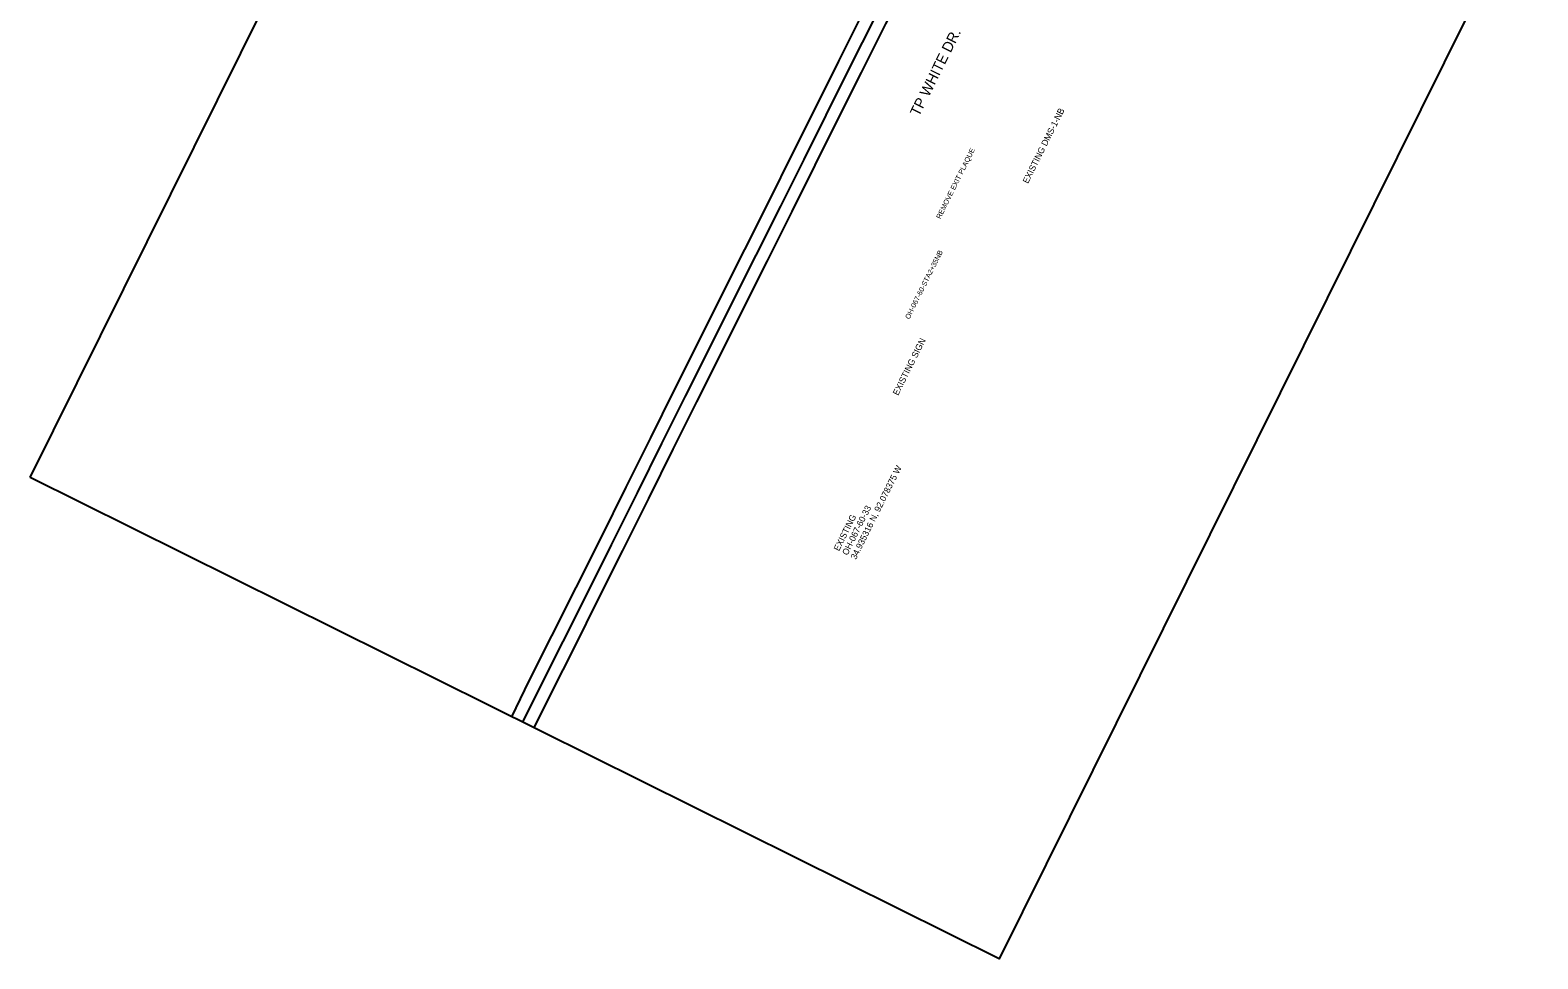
# Model space of a CAD drawing. Extents: x 1288247 to 1295361, y 218673 to 226414.
# Drawn here: x 1288247 to 1289679, y 218673 to 219555 of the extents above; entities that cross this region are included whole.
import ezdxf

# ---------------------------------------------------------------- set-up
doc = ezdxf.new("R2010")
doc.units = 0
for name, color, linetype in [('40', 7, 'Continuous'), ('Plan Notes', 7, 'Continuous'), ('R_Annotation', 7, 'Continuous'), ('R_No Plot', 7, 'Continuous'), ('R_Striping_Existing', 7, 'Continuous'), ('S_EDGE_PAVEMENT', 7, 'Continuous')]:
    doc.layers.add(name, color=color, linetype=linetype)

msp = doc.modelspace()

# ---------------------------------------------------------------- linework, layer by layer
at = {"layer": 'R_No Plot'}
msp.add_lwpolyline([(1288247.2, 219130.2), (1288758.7, 220160.2), (1289678.8, 219703.3), (1289167.3, 218673.3)], close=True, dxfattribs=at)
at = {"layer": 'R_Striping_Existing'}
for points in [[(1288704.4, 218903.1), (1288721.1, 218937.1), (1288742.4, 218979.7), (1288765.5, 219025.6), (1288788.6, 219071.6), (1288813.1, 219120.9), (1288836.4, 219167.7), (1288858.7, 219212.5), (1288881.1, 219257.4), (1288903.1, 219301.3), (1288925.8, 219346.5), (1288949.2, 219393.1), (1288971.2, 219437.3), (1288992.2, 219479.2), (1289015.1, 219525.1), (1289038.3, 219571.5), (1289061.2, 219617.1), (1289082.9, 219660.9), (1289105.4, 219706.1), (1289128.5, 219752.4), (1289151.4, 219798.2), (1289169.8, 219835.2), (1289192.8, 219881), (1289218.3, 219932)], [(1288715.1, 218897.8), (1288731.9, 218931.7), (1288753.2, 218974.3), (1288776.3, 219020.2), (1288799.3, 219066.3), (1288823.9, 219115.6), (1288847.1, 219162.3), (1288869.5, 219207.2), (1288891.9, 219252), (1288913.8, 219295.9), (1288936.6, 219341.1), (1288959.9, 219387.7), (1288982, 219431.9), (1289002.9, 219473.8), (1289025.9, 219519.7), (1289049.1, 219566.1), (1289071.9, 219611.8), (1289093.6, 219655.5), (1289116.2, 219700.7), (1289139.2, 219747), (1289162.1, 219792.9), (1289180.6, 219829.8), (1289203.5, 219875.6), (1289229, 219926.7)]]:
    msp.add_lwpolyline(points, dxfattribs=at)
at = {"layer": 'S_EDGE_PAVEMENT'}
msp.add_lwpolyline([(1288725.9, 218892.5), (1288742.6, 218926.4), (1288763.9, 218968.9), (1288787, 219014.9), (1288810, 219060.9), (1288834.6, 219110.2), (1288857.8, 219157), (1288880.2, 219201.8), (1288902.6, 219246.6), (1288924.5, 219290.6), (1288947.3, 219335.7), (1288970.6, 219382.4), (1288992.7, 219426.6), (1289013.6, 219468.5), (1289036.6, 219514.3), (1289059.8, 219560.7), (1289082.7, 219606.4), (1289104.4, 219650.2), (1289126.9, 219695.4), (1289150, 219741.7), (1289172.9, 219787.5), (1289191.3, 219824.4), (1289214.2, 219870.2), (1289239.7, 219921.3)], dxfattribs=at)

# ---------------------------------------------------------------- texts
at = {"layer": '40'}
msp.add_text('OH-067-60-STA2+35NB', height=4.8, rotation=63.5913, dxfattribs=at).set_placement((1289082, 219279.8))
at = {"layer": 'Plan Notes'}
msp.add_text('TP WHITE DR.', height=10, rotation=63.5913, dxfattribs=at).set_placement((1289091.1, 219472))
at = {"layer": 'R_Annotation'}
for s, height, p in [('EXISTING DMS-1-NB', 6, (1289194.6, 219408.5)), ('REMOVE EXIT PLAQUE', 4.8, (1289111.5, 219375)), ('EXISTING SIGN', 6, (1289071.3, 219207.4)), ('34.935316 N, 92.078375 W', 6, (1289031.3, 219051.7)), ('EXISTING', 6, (1289015.2, 219059.7)), ('OH-067-60-33', 6, (1289023.2, 219055.7))]:
    msp.add_text(s, height=height, rotation=63.5664, dxfattribs=at).set_placement(p)

doc.saveas('drawing.dxf')
